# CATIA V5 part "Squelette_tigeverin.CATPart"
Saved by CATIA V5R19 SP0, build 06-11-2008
Part number: Squelette_tigeverin
Bounding box of the stored display mesh (mm): x -500 to 500, y -2391.774 to 1443.75, z -1458.497 to 134.485
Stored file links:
  C:\Users\Guillaume et Fanny\Documents\IFMA\2A\IAO\Squelette_tigeverin.CATPart
  C:\Users\Guillaume et Fanny\Documents\IFMA\2A\IAO\Train d'aterrissage.CATProduct
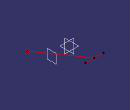
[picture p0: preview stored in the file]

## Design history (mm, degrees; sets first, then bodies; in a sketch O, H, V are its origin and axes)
Set1
  Point1: linked copy from another document
  Line1: linked copy from another document
  Point2: linked copy from another document
Body1 (main body)
  Line2: type PtDir, Direction (1, 0, 0), Start -500, End 500, RefPoint Point1
  Line3: type PtPt, SecondPoint Point1, FirstPoint Point2
  Plane1 "Plan.1010": type Offset, Offset 1010, RefPlane yz-plane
